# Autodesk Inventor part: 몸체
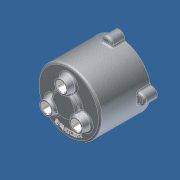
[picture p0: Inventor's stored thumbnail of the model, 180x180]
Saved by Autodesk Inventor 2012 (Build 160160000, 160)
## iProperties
Company: 한국ATC센터
Created: 2014-07
Part Number: 몸체
Document SubType Name: 모델링
Designer: KYOUNG IL JANG
Material: 기본값
Mass: 175.478 g
Surface Area: 687.662 cm^2
Volume: 175.478 cm^3
Density: 1 g/cm^3
변환 표준: STEP AP214IS
파일 이름: C:\Users\SeoGD\Desktop\?쒗뿕\紐몄껜.stp
전처리기: Build: 253, Release: 2010 SP1 - Date: Wed 07/29/2009
전송 단위: 밀리미터
불확실성: 0.01
Author: KYOUNG IL JANG
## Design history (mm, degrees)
sketch "스케치2"
  geometry: C1 r 50 at (0, 0); 1 further point
  constraints: 1 centre point, 1 coincident
  dimensions: "d9" = 100 diameter of C1
extrude "돌출2" new body sketch "스케치2" distance "d10" = 80; taper "d11" = 0 deg
feature "쉘1" dims "d12" = 5
sketch "스케치3" dims "d13" = 55
  geometry: C1 r 7.5 at (0, 27.5); C2 r 12.5 at (0, 27.5); 2 further points
  constraints: 2 centre point, 2 coincident, 2 vertical alignment, 2 other
  dimensions: "d14" = 15 diameter of C1; "d15" = 25 diameter of C2
extrude "돌출3" join sketch "스케치3" distance "d16" = 12; taper "d17" = -10 deg
hole "구멍2" diameter "d20" = 15; stored, may be unused: countersink angle "d24" = 90 deg, drill point angle "d26" = 118 deg; dims "d18" = 10, "d19" = 10, "d21" = 6, "d22" = 4, "d23" = 2, "d25" = 15
chamfer "모따기1" distance "d27" = 1; stored, may be unused: second distance "d28" = 2, angle "d29" = 45 deg
sketch "스케치4"
  geometry: L1 (0, 0)-(0, 88); L2 (0, 70)-(13.16, 70); L3 (-45, 75)-(45, 75) reference; L4 (-50, 80)-(50, 80) reference; L5 (13.16, 70)-(14.5, 75); L6 (20, 80)-(20, 88); L7 (20, 88)-(0, 88); L8 (20, 80)-(14.5, 75)
  constraints: 12 end point, 3 point on line, 2 perpendicular, 1 vertical
  dimensions: "d34" = 40 diameter of L6 L1; "d35" = 105 deg angle of L5 L3; "d36" = 5 distance between parallel lines of L2 L3; "d37" = 8 distance between parallel lines of L7 L4; "d51" = 29 diameter of L5.end L1
revolve "회전1" sketch "스케치4" stored, may be unused: angle "d38" = 90 deg
hole "구멍3" diameter "d41" = 15; stored, may be unused: countersink angle "d45" = 90 deg, drill point angle "d47" = 0 deg; dims "d39" = 10, "d40" = 10, "d42" = 6, "d43" = 22, "d44" = 13, "d46" = 15
chamfer "모따기2" distance "d48" = 1; stored, may be unused: second distance "d49" = 2, angle "d50" = 45 deg
fillet "모깎기1" dims "d52" = 3
fillet "모깎기2" dims "d53" = 3, "d72" = 0.2
sketch "스케치5"
  geometry: A1 r 50 centre (0, 0) between (50, 0) and (-8.074, 49.344) reference; A2 r 8.5 centre (0, 52) between (8.074, 49.344) and (-8.074, 49.344); 1 further point
  constraints: 5 point on circle, 1 centre point, 1 horizontal alignment
  dimensions: "d54" = 90 deg dimension on point (0, 0) A2.centre A1.start; "d55" = 52 distance of A2.centre point (0, 0); "d56" = 17 diameter of A2
extrude "돌출4" join sketch "스케치5" distance "d57" = 20; taper "d58" = 0 deg
fillet "모깎기3" dims "d59" = 3
hole "구멍4" diameter "d62" = 4.134; stored, may be unused: countersink angle "d66" = 90 deg, drill point angle "d68" = 118 deg; dims "d60" = 10, "d61" = 10, "d63" = 12, "d64" = 22, "d65" = 13, "d67" = 15
sketch "스케치6"
  geometry: C1 r 47 at (0, 0) reference; C2 r 42.5 at (0, 0); 1 further point
  constraints: 1 centre point, 1 coincident, 1 other
  dimensions: "d73" = 85 diameter of C2
feature "엠보싱1" sketch "스케치6" dims "d74" = 1, "d75" = 0
node "솔리드1"
node "솔리드 본체"
node "곡면 본체"
pattern_circular "원형 패턴1" dims "d31" = 360 deg
pattern_circular "원형 패턴2" dims "d70" = 360 deg
node "솔리드2"
